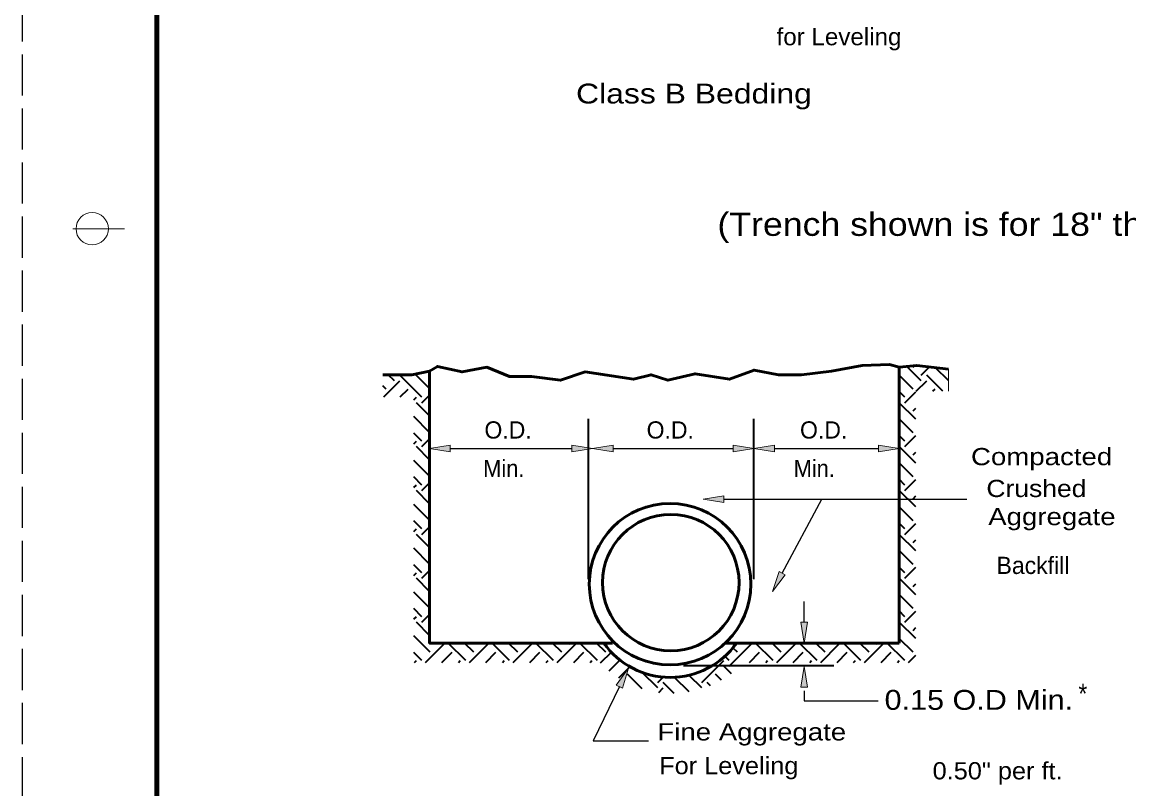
# Model space of a CAD drawing. Extents: x 36.1 to 71.5, y 0.2 to 22.2.
# Drawn here: x 37.71 to 46.27, y 10.68 to 16.61 of the extents above; entities that cross this region are included whole.
import ezdxf

# ---------------------------------------------------------------- set-up
doc = ezdxf.new("R2010")
doc.units = 0
doc.header["$LTSCALE"] = 0.053
doc.linetypes.add('LONG_DASHED', pattern=[7.5, 6, -1.5])
for name, color, linetype, lineweight in [('1', 7, 'Continuous', 35), ('3', 7, 'Continuous', 25), ('6', 7, 'Continuous', 13)]:
    doc.layers.add(name, color=color, linetype=linetype, lineweight=lineweight)

msp = doc.modelspace()

# ---------------------------------------------------------------- hatches: boundary and pattern name
at = {"layer": '1'}
for points in [[(41.02133, 13.28692), (41.02133, 13.34033), (40.86133, 13.31367), (40.86133, 13.31367)], [(41.95992, 13.28692), (41.95992, 13.34033), (42.11992, 13.31367), (42.11992, 13.31367)], [(42.27992, 13.28692), (42.27992, 13.34033), (42.11992, 13.31367), (42.11992, 13.31367)], [(43.20842, 13.28692), (43.20842, 13.34033), (43.36842, 13.31367), (43.36842, 13.31367)], [(43.52842, 13.28692), (43.52842, 13.34033), (43.36842, 13.31367), (43.36842, 13.31367)], [(44.33108, 13.28692), (44.33108, 13.34033), (44.49108, 13.31367), (44.49108, 13.31367)]]:
    msp.add_hatch(color=256, dxfattribs=at).paths.add_polyline_path(points)
at = {"layer": '3'}
for points in [[(43.13525, 12.89483), (43.13525, 12.94817), (42.97525, 12.9215), (42.97525, 12.9215)], [(43.61108, 12.33708), (43.56408, 12.36217), (43.51225, 12.20842), (43.51225, 12.20842)], [(43.78392, 11.96917), (43.73058, 11.96917), (43.75725, 11.80917), (43.75725, 11.80917)], [(42.30458, 11.48308), (42.35242, 11.45983), (42.39825, 11.6155), (42.39825, 11.6155)], [(43.78392, 11.46783), (43.73058, 11.46783), (43.75725, 11.62783), (43.75725, 11.62783)]]:
    msp.add_hatch(color=256, dxfattribs=at).paths.add_polyline_path(points)

# ---------------------------------------------------------------- linework, layer by layer
at = {"layer": '1', "linetype": 'LONG_DASHED', "lineweight": 25}
msp.add_line((37.71217, 22.21317), (37.71217, 0.21317), dxfattribs=at)
at = {"layer": '1', "lineweight": 158}
msp.add_line((38.75383, 21.71317), (38.75383, 0.71317), dxfattribs=at)
at = {"layer": '1', "lineweight": 13}
for p, q in [((38.50383, 15.01317), (38.10383, 15.01317)), ((44.87167, 13.92692), (44.87167, 13.75583)), ((40.86133, 13.35808), (40.86133, 13.54408)), ((43.36842, 12.30275), (43.36842, 13.54408)), ((44.49108, 13.24083), (44.49108, 13.08325)), ((43.82358, 11.80917), (43.98758, 11.80917))]:
    msp.add_line(p, q, dxfattribs=at)
at = {"layer": '1'}
for p, q in [((44.66242, 13.83717), (44.55192, 13.94758)), ((44.59883, 13.94325), (44.60917, 13.95358)), ((40.58958, 13.83717), (40.54242, 13.88417)), ((40.58958, 13.8795), (40.59417, 13.88417)), ((40.80158, 13.70983), (40.63192, 13.8795)), ((40.86133, 13.7775), (40.74958, 13.88925)), ((40.86133, 13.90475), (40.85475, 13.91133)), ((44.59883, 13.7735), (44.49108, 13.88125)), ((44.66242, 13.8795), (44.72675, 13.94383)), ((44.82858, 13.75583), (44.70492, 13.8795)), ((44.87167, 13.84), (44.77325, 13.9385)), ((40.52592, 13.7735), (40.501, 13.79825)), ((40.50783, 13.71308), (40.63192, 13.83717)), ((40.63508, 13.71308), (40.69558, 13.7735)), ((44.62358, 13.75583), (44.70492, 13.83717)), ((44.75083, 13.75583), (44.76858, 13.7735)), ((40.739, 13.68958), (40.75925, 13.70983)), ((40.80158, 13.66742), (40.86133, 13.72717)), ((44.53517, 13.70983), (44.49108, 13.75392)), ((44.49108, 13.70817), (44.49267, 13.70983)), ((44.53517, 13.66742), (44.62017, 13.7525)), ((40.86133, 13.56533), (40.75925, 13.66742)), ((44.62017, 13.53992), (44.49267, 13.66742)), ((44.59883, 13.60383), (44.62017, 13.62517)), ((40.86133, 13.43808), (40.739, 13.56042)), ((42.09017, 12.30275), (42.09017, 13.54408)), ((43.36842, 12.30275), (43.36842, 13.54408)), ((44.59883, 13.43417), (44.49108, 13.54183)), ((40.80158, 13.3705), (40.739, 13.43317)), ((40.739, 13.35017), (40.75925, 13.3705)), ((40.80158, 13.328), (40.86133, 13.38775)), ((44.53517, 13.3705), (44.49108, 13.4145)), ((44.49108, 13.36875), (44.49267, 13.3705)), ((44.53517, 13.328), (44.62017, 13.41317)), ((40.86133, 13.22592), (40.75925, 13.328)), ((44.62017, 13.2005), (44.49267, 13.328)), ((44.59883, 13.26442), (44.62017, 13.28575)), ((40.86133, 13.09867), (40.739, 13.221)), ((44.59883, 13.09475), (44.49108, 13.2025)), ((40.80158, 13.031), (40.739, 13.09375)), ((40.739, 13.01075), (40.75925, 13.031)), ((40.80158, 12.98858), (40.86133, 13.04833)), ((44.53517, 13.031), (44.49108, 13.07508)), ((44.49108, 13.02933), (44.49267, 13.031)), ((44.53517, 12.98858), (44.62017, 13.07367)), ((40.86133, 12.8865), (40.75925, 12.98858)), ((44.62017, 12.86117), (44.49267, 12.98858)), ((44.62017, 12.86117), (44.49267, 12.98858)), ((44.59883, 12.925), (44.62017, 12.94633)), ((40.86133, 12.75925), (40.739, 12.88158)), ((44.59883, 12.75525), (44.49108, 12.863)), ((40.80158, 12.69158), (40.739, 12.75433)), ((40.739, 12.67133), (40.75925, 12.69158)), ((40.80158, 12.64917), (40.86133, 12.70883)), ((44.53517, 12.69158), (44.49108, 12.73567)), ((44.49108, 12.68992), (44.49267, 12.69158)), ((44.53517, 12.64917), (44.62017, 12.73425)), ((40.86133, 12.54708), (40.75925, 12.64917)), ((44.62017, 12.52167), (44.49267, 12.64917)), ((44.59883, 12.58558), (44.62017, 12.60692)), ((40.86133, 12.41983), (40.739, 12.54217)), ((44.59883, 12.41583), (44.49108, 12.52358)), ((40.80158, 12.35217), (40.739, 12.41492)), ((40.739, 12.33192), (40.75925, 12.35217)), ((40.80158, 12.30975), (40.86133, 12.3695)), ((44.53517, 12.35217), (44.49108, 12.39625)), ((44.49108, 12.3505), (44.49267, 12.35217)), ((44.53517, 12.30975), (44.62017, 12.39483)), ((40.86133, 12.20767), (40.75925, 12.30975)), ((44.62017, 12.18225), (44.49267, 12.30975)), ((44.59883, 12.24617), (44.62017, 12.2675)), ((40.86133, 12.08042), (40.739, 12.20275)), ((44.59883, 12.0765), (44.49108, 12.18417)), ((40.80158, 12.01283), (40.739, 12.0755)), ((40.739, 11.9925), (40.75925, 12.01283)), ((40.80158, 11.97033), (40.86133, 12.03008)), ((44.53517, 12.01283), (44.49108, 12.05683)), ((44.49108, 12.01108), (44.49267, 12.01283)), ((44.53517, 11.97033), (44.62017, 12.0555)), ((40.86133, 11.86825), (40.75925, 11.97033)), ((44.62017, 11.84283), (44.49267, 11.97033)), ((44.59883, 11.90675), (44.62017, 11.92808)), ((40.86525, 11.73708), (40.739, 11.86333)), ((40.92892, 11.80058), (40.92042, 11.80917)), ((41.141, 11.67342), (41.00533, 11.80917)), ((41.20467, 11.73708), (41.13258, 11.80917)), ((41.26833, 11.80058), (41.25983, 11.80917)), ((41.48042, 11.67342), (41.34475, 11.80917)), ((41.54408, 11.73708), (41.472, 11.80917)), ((41.60767, 11.80058), (41.59925, 11.80917)), ((41.81983, 11.67342), (41.68417, 11.80917)), ((41.88358, 11.73708), (41.81142, 11.80917)), ((41.94708, 11.80058), (41.93867, 11.80917)), ((42.15925, 11.67342), (42.02358, 11.80917)), ((42.22292, 11.73708), (42.15083, 11.80917)), ((43.30475, 11.80058), (43.29633, 11.80917)), ((43.51692, 11.67342), (43.38125, 11.80917)), ((43.58058, 11.73708), (43.5085, 11.80917)), ((43.64417, 11.80058), (43.63575, 11.80917)), ((43.85633, 11.67342), (43.72058, 11.80917)), ((43.92, 11.73708), (43.84792, 11.80917)), ((43.98358, 11.80058), (43.97517, 11.80917)), ((44.19575, 11.67342), (44.06008, 11.80917)), ((44.25942, 11.73708), (44.18725, 11.80917)), ((44.323, 11.80058), (44.31458, 11.80917)), ((44.53517, 11.67342), (44.3995, 11.80917)), ((44.59883, 11.73708), (44.49108, 11.84483)), ((40.80158, 11.67342), (40.739, 11.73608)), ((40.83008, 11.65942), (40.97125, 11.80058)), ((40.95733, 11.65942), (41.035, 11.73708)), ((41.1695, 11.65942), (41.31075, 11.80058)), ((41.29675, 11.65942), (41.37442, 11.73708)), ((41.50892, 11.65942), (41.65017, 11.80058)), ((41.63617, 11.65942), (41.71383, 11.73708)), ((41.84833, 11.65942), (41.98958, 11.80058)), ((41.97558, 11.65942), (42.05325, 11.73708)), ((42.18383, 11.6555), (42.26933, 11.74117)), ((43.1775, 11.63092), (43.34725, 11.80058)), ((43.24117, 11.73708), (43.20942, 11.76875)), ((43.33325, 11.65942), (43.41092, 11.73708)), ((43.54525, 11.65942), (43.68658, 11.80058)), ((43.67258, 11.65942), (43.75025, 11.73708)), ((43.88467, 11.65942), (44.026, 11.80058)), ((44.01208, 11.65942), (44.08967, 11.73708)), ((44.22408, 11.65942), (44.36542, 11.80058)), ((44.3515, 11.65942), (44.42917, 11.73708)), ((40.74517, 11.65942), (40.75925, 11.67342)), ((41.08458, 11.65942), (41.09867, 11.67342)), ((41.424, 11.65942), (41.43808, 11.67342)), ((41.76342, 11.65942), (41.77742, 11.67342)), ((42.10283, 11.65942), (42.11683, 11.67342)), ((42.24983, 11.59417), (42.33558, 11.68)), ((42.96533, 11.50367), (43.135, 11.67342)), ((43.1775, 11.67342), (43.147, 11.70383)), ((43.4605, 11.65942), (43.4745, 11.67342)), ((43.79992, 11.65942), (43.81392, 11.67342)), ((44.13925, 11.65942), (44.15325, 11.67342)), ((44.47875, 11.65942), (44.49267, 11.67342)), ((44.56358, 11.65942), (44.62017, 11.71608)), ((42.32358, 11.54067), (42.41108, 11.62817)), ((42.504, 11.45583), (42.39258, 11.56733)), ((42.62592, 11.46117), (42.503, 11.58408)), ((42.96533, 11.46117), (42.86783, 11.55875)), ((42.90175, 11.56733), (42.90208, 11.56767)), ((43.11808, 11.52058), (43.0715, 11.56733)), ((43.19508, 11.571), (43.135, 11.63092)), ((42.62592, 11.50367), (42.66783, 11.54558)), ((42.75233, 11.41975), (42.66833, 11.50367)), ((42.8685, 11.43092), (42.75592, 11.5435)), ((43.03275, 11.47875), (43.00783, 11.50367)), ((43.03275, 11.47875), (43.00783, 11.50367)), ((42.63367, 11.42667), (42.66833, 11.46117))]:
    msp.add_line(p, q, dxfattribs=at)
at = {"layer": '1', "lineweight": 25}
for p, q in [((41.02133, 13.31367), (41.95992, 13.31367)), ((42.27992, 13.31367), (43.20842, 13.31367)), ((43.52842, 13.31367), (44.33108, 13.31367))]:
    msp.add_line(p, q, dxfattribs=at)
at = {"layer": '1', "lineweight": 53}
msp.add_line((43.154, 11.80917), (44.49108, 11.80917), dxfattribs=at)
for points in [[(40.86133, 13.91275), (40.9225, 13.94833), (41.11292, 13.90558), (41.30317, 13.94117), (41.47992, 13.86992), (41.64983, 13.86992), (41.87417, 13.84142), (42.06442, 13.90558), (42.43825, 13.8485), (42.57425, 13.88417), (42.70333, 13.84142), (42.91417, 13.89125), (43.17925, 13.8485), (43.3695, 13.91983), (43.55983, 13.88417), (43.73658, 13.88417), (43.96767, 13.91275), (44.20558, 13.9555), (44.41633, 13.96267), (44.49108, 13.94117)], [(44.49108, 11.80917), (44.49108, 13.94117), (44.627, 13.9555), (44.87167, 13.92692)], [(40.501, 13.88417), (40.72533, 13.88417), (40.86133, 13.91275), (40.86133, 11.80917), (42.27658, 11.80917)]]:
    msp.add_lwpolyline(points, dxfattribs=at)
at = {"layer": '1', "lineweight": 13}
for points in [[(41.02133, 13.28692), (41.02133, 13.34033), (40.86133, 13.31367), (40.86133, 13.31367)], [(41.95992, 13.28692), (41.95992, 13.34033), (42.11992, 13.31367), (42.11992, 13.31367)], [(42.27992, 13.28692), (42.27992, 13.34033), (42.11992, 13.31367), (42.11992, 13.31367)], [(43.20842, 13.28692), (43.20842, 13.34033), (43.36842, 13.31367), (43.36842, 13.31367)], [(43.52842, 13.28692), (43.52842, 13.34033), (43.36842, 13.31367), (43.36842, 13.31367)], [(44.33108, 13.28692), (44.33108, 13.34033), (44.49108, 13.31367), (44.49108, 13.31367)]]:
    msp.add_lwpolyline(points, close=True, dxfattribs=at)
msp.add_circle((38.25383, 15.01317), 0.125, dxfattribs=at)
at = {"layer": '1', "lineweight": 53}
for centre, radius in [((42.72028, 12.26437), 0.62428), ((42.72628, 12.27629), 0.52731)]:
    msp.add_circle(centre, radius, dxfattribs=at)
msp.add_arc((42.72123, 12.17033), 0.62758, 215.14084, 324.85915, dxfattribs=at)
at = {"layer": '3'}
for p, q in [((43.13525, 12.9215), (45.0145, 12.9215)), ((43.58758, 12.34967), (43.89292, 12.9215)), ((43.75725, 11.96917), (43.75725, 12.12917)), ((43.75725, 11.43842), (43.75725, 11.3615)), ((43.75725, 11.3615), (44.32967, 11.3615))]:
    msp.add_line(p, q, dxfattribs=at)
at = {"layer": '3', "lineweight": 35}
msp.add_line((42.82408, 11.63533), (43.98758, 11.63533), dxfattribs=at)
at = {"layer": '3', "lineweight": 13}
for points in [[(43.13525, 12.89483), (43.13525, 12.94817), (42.97525, 12.9215), (42.97525, 12.9215)], [(43.61108, 12.33708), (43.56408, 12.36217), (43.51225, 12.20842), (43.51225, 12.20842)], [(43.78392, 11.96917), (43.73058, 11.96917), (43.75725, 11.80917), (43.75725, 11.80917)], [(42.30458, 11.48308), (42.35242, 11.45983), (42.39825, 11.6155), (42.39825, 11.6155)], [(43.78392, 11.46783), (43.73058, 11.46783), (43.75725, 11.62783), (43.75725, 11.62783)]]:
    msp.add_lwpolyline(points, close=True, dxfattribs=at)
at = {"layer": '3'}
msp.add_lwpolyline([(42.32842, 11.4715), (42.12567, 11.05317), (42.55383, 11.05317)], dxfattribs=at)
at = {"layer": '6'}
for p, q in [((40.86133, 13.27808), (40.86142, 13.27808)), ((42.11992, 13.31367), (42.12, 13.31367)), ((43.36842, 13.31367), (43.36858, 13.31367)), ((44.49108, 13.32083), (44.49125, 13.32083)), ((44.49108, 13.31367), (44.49125, 13.31367)), ((42.11992, 12.22275), (42.12, 12.22275)), ((42.11992, 12.22275), (42.12, 12.22275)), ((43.36842, 12.22275), (43.36858, 12.22275)), ((43.36842, 12.22275), (43.36858, 12.22275)), ((43.74358, 11.80917), (43.74367, 11.80917)), ((43.75725, 11.80917), (43.75733, 11.80917)), ((42.74408, 11.59842), (42.74425, 11.59842))]:
    msp.add_line(p, q, dxfattribs=at)

# ---------------------------------------------------------------- texts
at = {"layer": '1'}
for p in [(41.28575, 13.3905), (42.53925, 13.3905), (43.72492, 13.3905)]:
    msp.add_text('O.D.', height=0.133, dxfattribs=at).set_placement(p)
at = {"layer": '3'}
for s, height, width, p in [('for Leveling', 0.133, 1.05, (43.54367, 16.43192)), ('Class B Bedding', 0.1536, 1.2, (41.994, 15.98167)), ('(Trench shown is for 18" thru 54" Pipe)', 0.1792, 1.15, (43.08658, 14.95792)), ('Compacted', 0.133, 1.2, (45.04675, 13.18425)), ('Min.', 0.133, 0.95, (41.27592, 13.09267)), ('Min.', 0.133, 0.95, (43.67542, 13.09267)), ('Crushed', 0.133, 1.15, (45.16567, 12.93808)), ('Aggregate', 0.133, 1.2, (45.17975, 12.7205)), ('*', 0.1536, 0.85, (45.87758, 11.3405)), ('0.15 O.D Min.', 0.1536, 1.15, (44.37858, 11.2925)), ('Fine Aggregate', 0.133, 1.2, (42.62242, 11.0555)), ('For Leveling', 0.133, 1.1, (42.63625, 10.79458)), ('0.50" per ft.', 0.133, 1.1, (44.74992, 10.7545))]:
    msp.add_text(s, height=height, dxfattribs=dict(at, width=width)).set_placement(p)
msp.add_text('Backfill', height=0.133, dxfattribs=at).set_placement((45.24408, 12.343))

doc.saveas('drawing.dxf')
